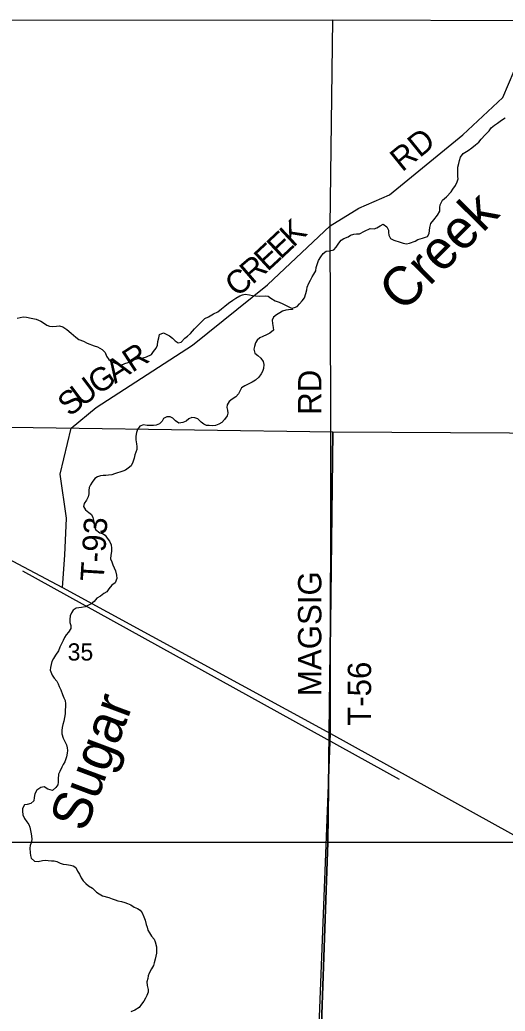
# Model space of a CAD drawing. Extents: x 1588073 to 2013523, y 1090242 to 1357120.
# Drawn here: x 1739887 to 1746125, y 1247940 to 1260685 of the extents above; entities that cross this region are included whole.
import ezdxf

# ---------------------------------------------------------------- set-up
doc = ezdxf.new("R2010")
doc.units = 0
for name, color, linetype in [('GM_X_Adjacent_County', 7, 'Continuous'), ('GM_X_County', 7, 'Continuous'), ('GM_X_Minor_River', 7, 'Continuous'), ('GM_X_Minor_River_Text', 7, 'Continuous'), ('GM_X_Section', 7, 'Continuous'), ('GM_X_Section_Text', 7, 'Continuous'), ('GM_X_State_Route', 7, 'Continuous'), ('GM_X_Township', 7, 'Continuous'), ('GM_X_Township_Road', 7, 'Continuous'), ('GM_X_Township_Road_Text', 7, 'Continuous'), ('GM_X_US_Route', 7, 'Continuous')]:
    doc.layers.add(name, color=color, linetype=linetype)

msp = doc.modelspace()

# ---------------------------------------------------------------- linework, layer by layer
at = {"layer": 'GM_X_Adjacent_County'}
msp.add_lwpolyline([(1738897, 1260682), (1743909, 1260685), (1746424, 1260676), (1747879, 1260667), (1749207, 1260664), (1751597, 1260643), (1751720, 1260643), (1752150, 1260647), (1752840, 1260654), (1753606, 1260661), (1753720, 1260662), (1754797, 1260665)], dxfattribs=at)
at = {"layer": 'GM_X_County'}
msp.add_lwpolyline([(1738897, 1260682), (1743909, 1260685), (1746424, 1260676), (1747879, 1260667), (1749207, 1260664), (1751597, 1260643), (1751720, 1260643), (1752150, 1260647), (1752840, 1260654), (1753606, 1260661), (1753720, 1260662), (1754797, 1260665)], dxfattribs=at)
at = {"layer": 'GM_X_Minor_River'}
msp.add_line((1744768, 1250918), (1739926, 1253597), dxfattribs=at)
for points in [[(1745257, 1258175), (1745285, 1258227), (1745284, 1258271), (1745288, 1258305), (1745319, 1258367), (1745371, 1258410), (1745430, 1258472), (1745453, 1258509), (1745487, 1258557), (1745508, 1258601), (1745522, 1258639), (1745516, 1258673), (1745515, 1258707), (1745517, 1258749), (1745518, 1258793), (1745528, 1258839), (1745540, 1258877), (1745551, 1258921), (1745583, 1258967), (1745648, 1259007), (1745698, 1259038), (1745745, 1259076), (1745787, 1259111), (1745815, 1259149), (1745868, 1259205), (1745919, 1259260), (1745943, 1259296), (1745987, 1259332), (1746026, 1259355), (1746078, 1259397), (1746127, 1259427)], [(1741578, 1256383), (1741604, 1256422), (1741641, 1256464), (1741655, 1256504), (1741661, 1256548), (1741672, 1256598), (1741684, 1256638), (1741733, 1256662), (1741778, 1256641), (1741812, 1256621), (1741848, 1256594), (1741884, 1256560), (1741923, 1256533), (1741960, 1256539), (1742006, 1256593), (1742044, 1256618), (1742079, 1256652), (1742133, 1256714), (1742166, 1256747), (1742212, 1256795), (1742265, 1256845), (1742311, 1256868), (1742376, 1256904), (1742432, 1256933), (1742478, 1256969), (1742521, 1257006), (1742569, 1257042), (1742626, 1257079), (1742662, 1257107), (1742714, 1257135), (1742748, 1257150), (1742785, 1257160), (1742839, 1257151), (1742878, 1257141), (1742918, 1257137), (1742968, 1257134), (1743039, 1257137), (1743077, 1257133), (1743112, 1257108), (1743170, 1257074), (1743220, 1257055), (1743268, 1257033), (1743303, 1257016), (1743337, 1256998), (1743377, 1256980), (1743419, 1256987), (1743453, 1257001), (1743482, 1257035), (1743514, 1257074), (1743545, 1257110), (1743563, 1257168), (1743574, 1257214), (1743582, 1257248), (1743601, 1257298), (1743625, 1257340), (1743645, 1257380), (1743666, 1257415), (1743690, 1257459), (1743697, 1257499), (1743711, 1257551), (1743728, 1257593), (1743754, 1257637), (1743785, 1257683), (1743825, 1257710), (1743869, 1257716), (1743921, 1257730), (1743952, 1257763), (1743986, 1257813), (1744019, 1257853), (1744053, 1257872), (1744105, 1257896), (1744139, 1257916), (1744180, 1257931), (1744214, 1257935), (1744254, 1257935), (1744318, 1257968), (1744390, 1258001), (1744440, 1257999), (1744477, 1258010), (1744519, 1258036), (1744559, 1258056), (1744605, 1258025), (1744626, 1257983), (1744626, 1257949), (1744628, 1257915), (1744653, 1257874), (1744693, 1257852), (1744775, 1257825), (1744813, 1257813), (1744855, 1257806), (1744897, 1257812), (1744969, 1257841), (1745003, 1257861), (1745064, 1257876), (1745126, 1257900), (1745148, 1257937), (1745153, 1257977), (1745155, 1258017), (1745168, 1258067), (1745210, 1258113), (1745257, 1258175)], [(1743389, 1256982), (1743391, 1256959), (1743339, 1256956), (1743305, 1256952), (1743265, 1256941), (1743228, 1256917), (1743186, 1256891), (1743148, 1256864), (1743131, 1256822), (1743135, 1256780), (1743144, 1256731), (1743148, 1256695), (1743102, 1256658), (1743059, 1256634), (1743011, 1256614), (1742973, 1256595), (1742939, 1256567), (1742918, 1256533), (1742904, 1256487), (1742895, 1256449), (1742909, 1256399), (1742947, 1256371), (1742986, 1256334), (1743016, 1256294), (1743025, 1256256), (1743021, 1256204), (1743006, 1256166), (1742988, 1256132), (1742960, 1256092), (1742917, 1256054), (1742873, 1256025), (1742829, 1256005), (1742778, 1255980), (1742738, 1255954), (1742697, 1255878), (1742663, 1255840), (1742618, 1255807), (1742578, 1255777), (1742552, 1255737), (1742549, 1255703), (1742555, 1255665), (1742559, 1255627), (1742550, 1255593), (1742518, 1255545), (1742483, 1255510), (1742445, 1255488), (1742401, 1255470), (1742361, 1255467), (1742319, 1255469), (1742285, 1255469), (1742251, 1255486), (1742217, 1255514), (1742174, 1255555), (1742136, 1255567), (1742098, 1255572), (1742061, 1255556), (1742023, 1255526), (1741981, 1255507), (1741933, 1255501), (1741887, 1255528), (1741855, 1255562), (1741818, 1255581), (1741775, 1255579), (1741735, 1255561), (1741715, 1255525), (1741683, 1255492), (1741640, 1255476), (1741604, 1255470), (1741566, 1255469), (1741522, 1255471), (1741476, 1255478), (1741430, 1255462), (1741400, 1255418), (1741385, 1255379), (1741379, 1255332), (1741378, 1255284), (1741388, 1255234), (1741393, 1255200), (1741389, 1255162), (1741379, 1255128), (1741366, 1255092), (1741358, 1255050), (1741341, 1255000), (1741317, 1254952), (1741280, 1254919), (1741246, 1254897), (1741212, 1254883), (1741103, 1254848), (1741069, 1254837), (1741027, 1254829), (1740993, 1254825), (1740959, 1254826), (1740923, 1254824), (1740885, 1254810), (1740851, 1254787), (1740816, 1254743), (1740794, 1254707), (1740779, 1254671), (1740773, 1254635), (1740773, 1254589), (1740766, 1254551)], [(1739855, 1256851), (1739931, 1256865), (1739975, 1256864), (1740035, 1256851), (1740097, 1256835), (1740157, 1256812), (1740191, 1256790), (1740233, 1256759), (1740268, 1256747), (1740312, 1256742), (1740359, 1256748), (1740397, 1256750), (1740441, 1256737), (1740490, 1256704), (1740548, 1256656), (1740609, 1256605), (1740647, 1256575), (1740707, 1256552), (1740753, 1256527), (1740844, 1256496), (1740886, 1256482), (1740944, 1256445), (1740983, 1256407), (1741001, 1256361), (1741031, 1256318), (1741066, 1256292), (1741144, 1256257), (1741190, 1256246), (1741236, 1256268), (1741321, 1256293), (1741357, 1256317), (1741429, 1256334), (1741471, 1256340), (1741515, 1256353), (1741578, 1256383)], [(1740766, 1254551), (1740746, 1254509), (1740715, 1254467), (1740707, 1254429), (1740730, 1254387), (1740774, 1254351), (1740810, 1254326), (1740827, 1254288), (1740833, 1254254), (1740837, 1254214), (1740846, 1254171), (1740862, 1254133), (1740915, 1254091), (1740949, 1254080), (1740985, 1254058), (1741011, 1254021), (1741038, 1253981), (1741060, 1253935), (1741065, 1253891), (1741067, 1253851), (1741057, 1253801), (1741054, 1253756), (1741070, 1253718), (1741083, 1253680), (1741099, 1253640), (1741117, 1253602), (1741130, 1253547), (1741136, 1253503), (1741113, 1253447), (1741071, 1253416), (1741030, 1253368), (1741006, 1253330), (1740969, 1253310), (1740923, 1253277), (1740879, 1253251), (1740844, 1253207), (1740804, 1253176), (1740770, 1253158), (1740725, 1253139), (1740681, 1253131), (1740647, 1253127), (1740613, 1253120), (1740575, 1253096), (1740551, 1253060), (1740534, 1253022), (1740532, 1252976), (1740531, 1252938), (1740541, 1252900), (1740542, 1252858), (1740512, 1252814), (1740482, 1252778), (1740461, 1252744), (1740445, 1252705), (1740428, 1252671), (1740402, 1252621), (1740385, 1252571), (1740345, 1252517), (1740318, 1252473), (1740300, 1252435), (1740283, 1252359), (1740279, 1252323), (1740302, 1252259), (1740328, 1252221), (1740361, 1252182), (1740381, 1252148), (1740395, 1252114), (1740416, 1252073), (1740436, 1252011), (1740455, 1251969), (1740469, 1251935), (1740474, 1251890), (1740474, 1251856), (1740472, 1251808), (1740469, 1251762), (1740461, 1251716), (1740452, 1251668), (1740440, 1251624), (1740433, 1251588), (1740429, 1251550), (1740428, 1251504), (1740444, 1251450), (1740467, 1251408), (1740487, 1251363), (1740497, 1251327), (1740500, 1251293), (1740496, 1251257), (1740487, 1251209), (1740465, 1251147), (1740446, 1251111), (1740426, 1251077), (1740401, 1251023), (1740383, 1250988), (1740382, 1250921), (1740380, 1250885), (1740376, 1250851), (1740349, 1250816), (1740307, 1250778), (1740249, 1250792), (1740201, 1250823), (1740157, 1250817), (1740105, 1250782)], [(1740105, 1250782), (1740082, 1250736), (1740072, 1250688), (1740067, 1250646), (1740029, 1250608), (1739983, 1250597), (1739949, 1250593), (1739922, 1250545), (1739920, 1250511), (1739925, 1250465), (1739949, 1250415), (1739976, 1250376), (1740002, 1250340), (1740016, 1250306), (1740027, 1250240), (1740039, 1250193), (1740040, 1250145), (1740032, 1250105), (1740021, 1250069), (1740017, 1250035), (1740020, 1249977), (1740026, 1249941), (1740034, 1249907), (1740075, 1249868), (1740121, 1249864), (1740177, 1249879), (1740219, 1249883), (1740253, 1249878), (1740293, 1249874), (1740329, 1249872), (1740363, 1249863), (1740405, 1249841), (1740445, 1249828), (1740487, 1249824), (1740539, 1249815), (1740573, 1249809), (1740607, 1249789), (1740630, 1249738), (1740654, 1249700), (1740677, 1249656), (1740701, 1249615), (1740737, 1249581), (1740772, 1249552), (1740822, 1249522), (1740874, 1249471), (1740907, 1249449), (1740951, 1249422), (1741031, 1249402), (1741073, 1249383), (1741113, 1249371), (1741147, 1249358), (1741193, 1249348), (1741237, 1249337), (1741272, 1249325), (1741312, 1249308), (1741358, 1249276), (1741400, 1249261), (1741436, 1249239), (1741461, 1249205), (1741483, 1249152), (1741498, 1249108), (1741512, 1249054), (1741523, 1249018), (1741533, 1248983), (1741553, 1248947), (1741578, 1248905), (1741612, 1248864), (1741628, 1248830), (1741643, 1248766), (1741645, 1248726), (1741642, 1248686), (1741634, 1248646), (1741627, 1248608), (1741615, 1248562), (1741606, 1248526), (1741578, 1248486), (1741551, 1248430), (1741537, 1248396), (1741533, 1248358), (1741520, 1248318), (1741524, 1248270), (1741537, 1248218), (1741537, 1248184), (1741518, 1248140), (1741504, 1248106), (1741480, 1248070), (1741449, 1248028), (1741419, 1247988), (1741364, 1247953), (1741316, 1247933)]]:
    msp.add_lwpolyline(points, dxfattribs=at)
at = {"layer": 'GM_X_Section'}
for points in [[(1738572, 1255464), (1743908, 1255388), (1743847, 1250108), (1738584, 1250111)], [(1743908, 1255388), (1749207, 1255359), (1749184, 1250112), (1743847, 1250108)], [(1738584, 1250111), (1743847, 1250108), (1743652, 1244580), (1738401, 1244619)], [(1743847, 1250108), (1749184, 1250112), (1749046, 1244692), (1743652, 1244580)]]:
    msp.add_lwpolyline(points, close=True, dxfattribs=at)
at = {"layer": 'GM_X_State_Route'}
msp.add_lwpolyline([(1743467, 1239272), (1743467, 1239272), (1743550, 1241949), (1743712, 1247202), (1743882, 1251508)], dxfattribs=at)
at = {"layer": 'GM_X_Township'}
msp.add_lwpolyline([(1738897, 1260682), (1743909, 1260685), (1746424, 1260676), (1747879, 1260667), (1749207, 1260664), (1749198, 1260142), (1749198, 1260116), (1749203, 1258015), (1749180, 1254042), (1749133, 1248594), (1749049, 1246137)], dxfattribs=at)
at = {"layer": 'GM_X_Township_Road'}
for points in [[(1743875, 1258037), (1743909, 1260685)], [(1743875, 1258037), (1744246, 1258263), (1744639, 1258437), (1745582, 1259208), (1746095, 1259687), (1746240, 1260031), (1746261, 1260355), (1746280, 1260457), (1746310, 1260530), (1746337, 1260572), (1746376, 1260617), (1746424, 1260676)], [(1740435, 1253387), (1740465, 1253802), (1740487, 1254279), (1740406, 1254842), (1740549, 1255435), (1740868, 1255702), (1742106, 1256502), (1743069, 1257276), (1743875, 1258037)], [(1743882, 1251508), (1743883, 1255647), (1743875, 1258037)]]:
    msp.add_lwpolyline(points, dxfattribs=at)
at = {"layer": 'GM_X_US_Route'}
msp.add_lwpolyline([(1735028, 1256329), (1737239, 1255105), (1739653, 1253802), (1740435, 1253387), (1743882, 1251508), (1746472, 1250074), (1748853, 1248750), (1748853, 1248750)], dxfattribs=at)

# ---------------------------------------------------------------- texts
at = {"layer": 'GM_X_Minor_River_Text'}
for s, rotation, p in [('Creek', 45.0495, (1744810, 1256912)), ('Sugar', 69.5014, (1740727, 1250228))]:
    msp.add_text(s, height=500.3, rotation=rotation, dxfattribs=at).set_placement(p)
at = {"layer": 'GM_X_Section_Text'}
msp.add_text('35', height=221, rotation=0, dxfattribs=at).set_placement((1740502, 1252448))
at = {"layer": 'GM_X_Township_Road_Text'}
for s, rotation, p in [('RD', 39.0451, (1744801, 1258722)), ('K', 43.1915, (1743401, 1257750)), ('E', 43.188, (1743237, 1257596)), ('E', 42.8246, (1743071, 1257442)), ('R', 40.7951, (1742876, 1257274)), ('C', 39.0475, (1742677, 1257112)), ('R', 32.8349, (1741332, 1256145)), ('A', 32.8383, (1741110, 1256001)), ('G', 33.3102, (1740890, 1255857)), ('U', 36.8408, (1740683, 1255701)), ('RD', 90, (1743763, 1255607)), ('S', 39.9674, (1740531, 1255574)), ('T-93', 86.4676, (1740964, 1253459)), ('MAGSIG', 90, (1743763, 1251991)), ('T-56', 90, (1744402, 1251608))]:
    msp.add_text(s, height=300, rotation=rotation, dxfattribs=at).set_placement(p)

doc.saveas('drawing.dxf')
